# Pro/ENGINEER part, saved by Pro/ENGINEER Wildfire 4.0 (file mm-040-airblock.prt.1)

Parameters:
  METRIC = "NO"

Other parameters: PITCH, DRILL_POINT_ANGLE, DRILL_DEPTH, DRILL_DIAMETER, THREAD_DIAMETER, THREADS_PER_INCH, THREAD_DEPTH, THREAD_LENGTH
